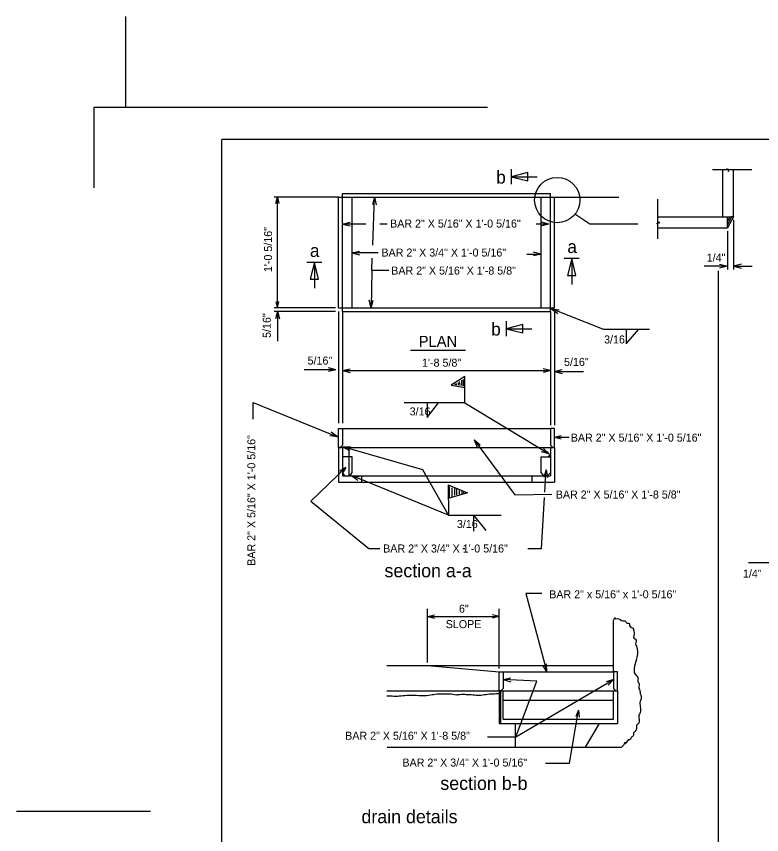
# Model space of a CAD drawing. Extents: x 973.2 to 1069.7, y 1484.4 to 1549.5.
# Drawn here: x 973.24 to 1004.28, y 1515.43 to 1549.5 of the extents above; entities that cross this region are included whole.
import ezdxf

# ---------------------------------------------------------------- set-up
doc = ezdxf.new("R2010")
doc.units = 0
for name, color, linetype in [('Level 1', 7, 'Continuous'), ('Level 2', 7, 'Continuous'), ('Level 37', 7, 'Continuous')]:
    doc.layers.add(name, color=color, linetype=linetype)

msp = doc.modelspace()

# ---------------------------------------------------------------- linework, layer by layer
at = {"layer": 'Level 1'}
for p, q in [((992.855, 1545.696), (976.473, 1545.696)), ((976.473, 1545.696), (976.473, 1542.36)), ((981.8, 1488.431), (981.8, 1544.364)), ((1065.368, 1544.364), (981.8, 1544.364)), ((993.409, 1520.047), (993.409, 1521.427))]:
    msp.add_line(p, q, dxfattribs=at)
at = {"layer": 'Level 2'}
for p, q in [((977.804, 1545.696), (977.804, 1549.495)), ((993.843, 1543.13), (993.843, 1542.506)), ((1002.223, 1543.118), (1002.829, 1543.118)), ((1002.666, 1541.155), (1002.666, 1543.122)), ((1002.829, 1543.118), (1002.853, 1543.163)), ((1002.853, 1543.163), (1002.898, 1543.04)), ((1002.898, 1543.04), (1002.905, 1543.118)), ((1002.905, 1543.118), (1003.872, 1543.118)), ((1003.1, 1541.155), (1003.1, 1543.122)), ((993.843, 1542.818), (994.921, 1542.818)), ((986.661, 1541.961), (983.97, 1541.961)), ((984.11, 1537.367), (984.11, 1541.961)), ((986.661, 1541.961), (995.651, 1541.961)), ((986.661, 1537.367), (986.661, 1541.961)), ((986.824, 1542.124), (995.487, 1542.124)), ((986.824, 1537.203), (986.824, 1542.124)), ((987.218, 1537.367), (987.218, 1541.961)), ((988.159, 1541.961), (988.068, 1541.649)), ((988.079, 1539.964), (988.159, 1541.961)), ((988.159, 1541.961), (988.225, 1541.643)), ((995.093, 1537.367), (995.093, 1541.961)), ((995.487, 1537.203), (995.487, 1542.124)), ((995.651, 1537.367), (995.651, 1541.961)), ((995.651, 1541.961), (998.335, 1541.961)), ((999.958, 1540.92), (999.958, 1541.888)), ((996.497, 1541.273), (997.126, 1540.854)), ((986.825, 1540.85), (987.14, 1540.928)), ((995.409, 1540.85), (995.126, 1540.921)), ((999.913, 1540.869), (1000.036, 1540.914)), ((999.958, 1541.155), (1003.1, 1541.155)), ((1000.036, 1540.914), (999.958, 1540.92)), ((1003.032, 1541.172), (1002.855, 1540.833)), ((1003.1, 1541.155), (1002.855, 1540.687)), ((1002.855, 1540.687), (1002.855, 1541.137)), ((1002.954, 1541.161), (1002.864, 1540.989)), ((1003.1, 1541.025), (1003.1, 1538.96)), ((986.825, 1540.85), (987.14, 1540.771)), ((987.791, 1540.85), (986.825, 1540.85)), ((988.682, 1540.85), (988.38, 1540.85)), ((995.409, 1540.85), (994.885, 1540.85)), ((995.409, 1540.85), (995.126, 1540.779)), ((997.126, 1540.854), (999.126, 1540.854)), ((999.958, 1540.845), (999.913, 1540.869)), ((999.958, 1540.239), (999.958, 1540.845)), ((999.958, 1540.687), (1002.855, 1540.687)), ((1002.855, 1540.557), (1002.855, 1538.96)), ((987.218, 1539.647), (987.533, 1539.726)), ((988.306, 1539.647), (987.218, 1539.647)), ((987.218, 1539.647), (987.533, 1539.568)), ((994.504, 1539.598), (995.095, 1539.598)), ((995.095, 1539.598), (994.78, 1539.676)), ((995.095, 1539.598), (994.78, 1539.519)), ((985.962, 1539.252), (985.338, 1539.252)), ((985.65, 1539.252), (985.65, 1538.173)), ((988.036, 1538.91), (988.057, 1539.425)), ((996.68, 1539.414), (996.056, 1539.414)), ((996.368, 1539.414), (996.368, 1538.336)), ((988.036, 1538.91), (988.012, 1537.367)), ((988.749, 1538.91), (988.036, 1538.91)), ((1002.855, 1539.09), (1001.878, 1539.09)), ((1002.483, 1514.351), (1002.483, 1538.904)), ((1003.1, 1539.09), (1003.882, 1539.09)), ((988.012, 1537.367), (987.938, 1537.683)), ((988.012, 1537.367), (988.095, 1537.68)), ((986.529, 1537.367), (983.978, 1537.367)), ((986.529, 1537.203), (983.978, 1537.203)), ((984.116, 1537.217), (984.037, 1536.902)), ((984.116, 1537.217), (984.116, 1535.973)), ((984.116, 1537.217), (984.195, 1536.902)), ((986.661, 1537.367), (995.651, 1537.367)), ((986.661, 1537.203), (986.661, 1532.565)), ((986.824, 1537.203), (995.487, 1537.203)), ((986.824, 1537.203), (986.824, 1532.565)), ((995.487, 1537.203), (995.487, 1532.474)), ((997.66, 1536.477), (995.524, 1537.315)), ((995.524, 1537.315), (995.846, 1537.273)), ((995.524, 1537.315), (995.788, 1537.126)), ((995.651, 1537.203), (995.651, 1532.474)), ((993.633, 1536.802), (993.633, 1536.178)), ((993.633, 1536.49), (994.711, 1536.49)), ((997.66, 1536.477), (999.599, 1536.477)), ((998.635, 1536.477), (998.635, 1535.86)), ((998.635, 1535.86), (999.157, 1536.477)), ((989.657, 1535.596), (991.94, 1535.596)), ((986.548, 1534.786), (985.231, 1534.786)), ((986.548, 1534.786), (986.233, 1534.865)), ((986.548, 1534.786), (986.233, 1534.707)), ((986.824, 1534.745), (987.139, 1534.824)), ((995.487, 1534.745), (995.172, 1534.824)), ((995.651, 1534.71), (995.966, 1534.789)), ((986.824, 1534.745), (995.487, 1534.745)), ((986.824, 1534.745), (987.139, 1534.666)), ((991.92, 1534.495), (991.353, 1534.145)), ((991.92, 1533.408), (991.92, 1534.495)), ((995.487, 1534.745), (995.172, 1534.666)), ((995.651, 1534.71), (996.858, 1534.71)), ((995.651, 1534.71), (995.966, 1534.631)), ((991.353, 1534.145), (991.92, 1534.041)), ((991.523, 1534.145), (991.495, 1534.202)), ((991.57, 1534.145), (991.57, 1534.212)), ((991.655, 1534.145), (991.655, 1534.24)), ((991.722, 1534.127), (991.693, 1534.287)), ((991.797, 1534.127), (991.797, 1534.354)), ((991.863, 1534.098), (991.863, 1534.372)), ((983.102, 1532.724), (983.102, 1533.413)), ((983.102, 1533.413), (986.613, 1531.987)), ((991.92, 1533.408), (989.387, 1533.408)), ((990.351, 1533.408), (990.351, 1532.791)), ((990.351, 1532.791), (990.814, 1533.408)), ((991.92, 1533.408), (995.421, 1531.276)), ((986.613, 1531.987), (986.291, 1532.033)), ((986.613, 1531.987), (986.35, 1532.179)), ((986.661, 1531.546), (986.661, 1532.334)), ((986.661, 1532.334), (986.824, 1532.334)), ((986.824, 1532.334), (995.487, 1532.334)), ((986.825, 1532.334), (986.825, 1531.64)), ((995.486, 1532.334), (995.486, 1531.64)), ((995.65, 1532.334), (995.487, 1532.334)), ((995.65, 1531.546), (995.65, 1532.334)), ((995.65, 1531.978), (995.934, 1532.046)), ((992.308, 1531.865), (994.002, 1529.581)), ((992.308, 1531.865), (992.559, 1531.658)), ((992.308, 1531.865), (992.432, 1531.565)), ((995.65, 1531.978), (996.258, 1531.973)), ((995.65, 1531.978), (995.933, 1531.904)), ((986.661, 1531.546), (995.651, 1531.546)), ((986.661, 1531.546), (986.661, 1530.103)), ((986.73, 1531.546), (986.661, 1531.546)), ((986.825, 1531.64), (986.73, 1531.546)), ((986.748, 1531.546), (986.824, 1531.546)), ((986.824, 1531.546), (986.824, 1530.365)), ((990.169, 1530.61), (986.839, 1531.58)), ((986.839, 1531.58), (987.164, 1531.568)), ((986.839, 1531.58), (987.119, 1531.417)), ((987.084, 1531.546), (987.084, 1530.365)), ((995.421, 1531.276), (995.111, 1531.372)), ((995.421, 1531.276), (995.193, 1531.507)), ((995.486, 1531.64), (995.581, 1531.546)), ((995.487, 1531.546), (995.487, 1530.365)), ((995.581, 1531.546), (995.65, 1531.546)), ((995.651, 1531.546), (995.651, 1530.103)), ((987.218, 1531.153), (986.824, 1531.153)), ((986.824, 1531.153), (986.824, 1530.488)), ((987.218, 1530.498), (987.218, 1531.153)), ((995.094, 1530.497), (995.094, 1531.153)), ((995.094, 1531.153), (995.487, 1531.153)), ((995.394, 1531.153), (995.488, 1531.248)), ((995.488, 1531.153), (995.488, 1530.497)), ((986.963, 1530.708), (985.502, 1529.31)), ((986.963, 1530.708), (986.709, 1530.563)), ((986.963, 1530.708), (986.807, 1530.46)), ((986.824, 1530.488), (986.931, 1530.365)), ((986.824, 1530.365), (995.487, 1530.365)), ((986.931, 1530.365), (987.124, 1530.365)), ((987.124, 1530.365), (987.218, 1530.498)), ((991.231, 1528.722), (987.201, 1530.381)), ((987.201, 1530.381), (987.522, 1530.334)), ((987.201, 1530.381), (987.462, 1530.189)), ((987.612, 1530.382), (987.612, 1530.114)), ((991.231, 1528.722), (990.169, 1530.61)), ((994.7, 1530.357), (994.7, 1530.114)), ((995.094, 1530.497), (995.188, 1530.366)), ((995.356, 1530.366), (995.188, 1530.366)), ((995.303, 1530.612), (995.206, 1530.303)), ((995.248, 1529.69), (995.303, 1530.612)), ((995.303, 1530.612), (995.363, 1530.293)), ((995.356, 1530.366), (995.488, 1530.497)), ((986.661, 1530.103), (995.651, 1530.103)), ((991.222, 1529.998), (991.231, 1528.722)), ((991.222, 1529.998), (992.025, 1529.657)), ((992.025, 1529.657), (991.226, 1529.421)), ((991.274, 1529.459), (991.274, 1529.918)), ((991.387, 1529.506), (991.387, 1529.87)), ((991.501, 1529.558), (991.501, 1529.847)), ((991.586, 1529.577), (991.586, 1529.804)), ((991.69, 1529.605), (991.69, 1529.761)), ((991.803, 1529.62), (991.803, 1529.743)), ((991.874, 1529.643), (991.874, 1529.686)), ((985.502, 1529.31), (987.915, 1527.347)), ((994.002, 1529.581), (995.536, 1529.596)), ((995.108, 1527.347), (995.235, 1529.47)), ((991.231, 1528.722), (993.433, 1528.722)), ((992.271, 1528.722), (992.271, 1528.061)), ((992.271, 1528.722), (992.796, 1528.088)), ((987.915, 1527.347), (988.375, 1527.347)), ((991.83, 1527.347), (991.918, 1527.347)), ((994.546, 1527.347), (995.108, 1527.347)), ((1003.734, 1526.756), (1005.349, 1526.756)), ((995.12, 1525.468), (994.457, 1525.468)), ((994.457, 1525.468), (995.332, 1522.209)), ((990.365, 1522.601), (990.365, 1524.831)), ((990.372, 1524.509), (990.655, 1524.58)), ((993.351, 1524.509), (993.067, 1524.58)), ((993.351, 1522.34), (993.351, 1524.831)), ((990.372, 1524.509), (993.351, 1524.509)), ((990.372, 1524.509), (990.655, 1524.439)), ((993.351, 1524.509), (993.067, 1524.439)), ((998.109, 1522.471), (998.109, 1524.34)), ((995.332, 1522.209), (995.318, 1522.533)), ((988.661, 1522.471), (998.109, 1522.471)), ((990.365, 1522.471), (993.351, 1522.209)), ((993.351, 1521.421), (993.351, 1522.209)), ((993.351, 1522.209), (993.514, 1522.209)), ((993.515, 1522.209), (998.109, 1522.209)), ((993.515, 1522.209), (993.515, 1521.516)), ((995.332, 1522.209), (995.167, 1522.489)), ((998.109, 1522.209), (998.109, 1522.471)), ((998.272, 1522.209), (998.109, 1522.209)), ((998.109, 1522.209), (998.109, 1521.516)), ((998.272, 1521.421), (998.272, 1522.209)), ((993.515, 1521.887), (993.833, 1521.949)), ((994.911, 1521.813), (993.515, 1521.887)), ((993.515, 1521.887), (993.825, 1521.792)), ((994.035, 1519.5), (998.109, 1521.887)), ((994.035, 1519.5), (994.911, 1521.813)), ((998.109, 1521.887), (997.799, 1521.788)), ((998.109, 1521.887), (997.883, 1521.654)), ((993.515, 1521.516), (993.42, 1521.421)), ((998.109, 1521.516), (998.203, 1521.421)), ((988.661, 1521.421), (998.273, 1521.421)), ((993.42, 1521.421), (993.351, 1521.421)), ((993.351, 1521.421), (993.351, 1520.056)), ((993.515, 1521.421), (998.109, 1521.421)), ((993.515, 1521.028), (993.515, 1521.421)), ((998.109, 1521.028), (998.109, 1521.421)), ((998.203, 1521.421), (998.272, 1521.421)), ((998.273, 1521.421), (998.273, 1520.056)), ((993.515, 1521.028), (998.109, 1521.028)), ((993.515, 1520.24), (993.515, 1521.028)), ((998.109, 1520.24), (998.109, 1521.028)), ((996.28, 1518.41), (996.648, 1520.61)), ((996.648, 1520.61), (996.531, 1520.342)), ((996.648, 1520.61), (996.671, 1520.318)), ((993.515, 1520.24), (998.109, 1520.24)), ((993.351, 1520.056), (998.273, 1520.056)), ((994.012, 1520.056), (994.012, 1519.067)), ((997.505, 1520.056), (996.933, 1519.071)), ((992.858, 1519.5), (994.035, 1519.5)), ((988.677, 1519.071), (998.458, 1519.071)), ((995.275, 1518.41), (996.28, 1518.41))]:
    msp.add_line(p, q, dxfattribs=at)
for points in [[(994.546, 1542.994), (993.843, 1542.818), (994.546, 1542.642)], [(985.826, 1538.548), (985.65, 1539.252), (985.475, 1538.548)], [(996.544, 1538.711), (996.368, 1539.414), (996.192, 1538.711)], [(994.336, 1536.666), (993.633, 1536.49), (994.336, 1536.315)]]:
    msp.add_lwpolyline(points, close=True, dxfattribs=at)
for points in [[(984.044, 1541.698), (984.11, 1541.961), (984.175, 1541.698)], [(1002.521, 1539.174), (1002.855, 1539.09), (1002.521, 1539.007)], [(1003.434, 1539.174), (1003.1, 1539.09), (1003.434, 1539.007)], [(984.044, 1537.629), (984.11, 1537.367), (984.175, 1537.629)]]:
    msp.add_lwpolyline(points, dxfattribs=at)
msp.add_circle((995.763, 1541.848), 0.944, dxfattribs=at)
for points in [[(998.109, 1524.34), (998.172, 1524.452), (998.172, 1524.42), (998.267, 1524.42), (998.489, 1524.325), (998.585, 1524.325), (998.68, 1524.23), (998.743, 1524.23), (998.775, 1524.166), (998.775, 1524.134), (998.934, 1523.976), (998.934, 1523.944), (998.966, 1523.849), (998.966, 1523.595), (999.029, 1523.563), (999.029, 1523.372), (999.061, 1523.277), (999.061, 1522.737), (999.061, 1522.039), (999.125, 1521.975), (999.125, 1521.785), (999.156, 1521.753), (999.156, 1521.562), (999.22, 1521.372), (999.22, 1521.308), (999.252, 1521.213), (999.252, 1521.181), (999.252, 1521.086), (999.22, 1520.991), (999.22, 1520.514), (999.156, 1520.356), (999.156, 1520.07), (999.125, 1520.038), (999.061, 1519.943), (999.061, 1519.879), (999.029, 1519.752), (998.934, 1519.657), (998.934, 1519.562), (998.839, 1519.467), (998.775, 1519.371), (998.743, 1519.371), (998.585, 1519.213), (998.585, 1519.276), (998.553, 1519.213), (998.489, 1519.117), (998.454, 1519.091)], [(991.56, 1521.236), (991.269, 1521.277), (990.962, 1521.277), (990.683, 1521.263), (990.418, 1521.221), (989.582, 1521.221), (989.261, 1521.193), (988.661, 1521.193)], [(993.351, 1521.292), (993.072, 1521.279), (992.798, 1521.255), (992.518, 1521.217), (992.251, 1521.236), (991.977, 1521.255), (991.71, 1521.255), (991.56, 1521.236)]]:
    msp.add_spline(points, degree=3, dxfattribs=at)
at = {"layer": 'Level 37'}
msp.add_line((978.831, 1516.397), (973.24, 1516.397), dxfattribs=at)

# ---------------------------------------------------------------- texts
at = {"layer": 'Level 2'}
for s, height, rotation, p in [('b ', 0.5333, 360, (993.225, 1542.534)), ('1\'-0 5/16"', 0.3333, 90, (983.887, 1538.847)), ('a ', 0.5333, 360, (985.466, 1539.479)), ('a ', 0.5333, 360, (996.184, 1539.642)), ('5/16"', 0.3333, 90, (983.835, 1536.108)), ('b ', 0.5333, 360, (993.015, 1536.206)), ('BAR 2" X 5/16" X 1\'-0 5/16"', 0.33333, 90, (983.192, 1526.621)), ('BAR 2" X 5/16" X 1\'-0 5/16"', 0.33333, 360, (996.326, 1531.79))]:
    msp.add_text(s, height=height, rotation=rotation, dxfattribs=at).set_placement(p)
for s, height, p in [('BAR 2" X 5/16" X 1\'-0 5/16"', 0.33333, (988.802, 1540.702)), ('BAR 2" X 3/4" X 1\'-0 5/16"', 0.33333, (988.442, 1539.496)), ('1/4" ', 0.3333, (1001.988, 1539.285)), ('BAR 2" X 5/16" X 1\'-8 5/8"', 0.33333, (988.851, 1538.745)), ('PLAN', 0.4593, (989.993, 1535.735)), ('3/16', 0.3333, (997.714, 1535.877)), ('5/16"', 0.3333, (985.367, 1534.998)), ('1\'-8 5/8"', 0.3333, (990.132, 1534.909)), ('5/16"', 0.3333, (996.046, 1534.941)), ('3/16', 0.3333, (989.618, 1532.882)), ('BAR 2" X 5/16" X 1\'-8 5/8"', 0.33333, (995.702, 1529.421)), ('3/16', 0.3333, (991.586, 1528.193)), ('BAR 2" X 3/4" X 1\'-0 5/16"', 0.33333, (988.513, 1527.174)), ('section a-a', 0.555, (988.571, 1526.142)), ('1/4"', 0.3333, (1003.496, 1526.132)), ('BAR 2" x 5/16" x 1\'-0 5/16"', 0.33333, (995.428, 1525.267)), ('6"', 0.3333, (991.671, 1524.669)), ('SLOPE', 0.3333, (991.12, 1524.025)), ('BAR 2" X 5/16" X 1\'-8 5/8"', 0.33333, (986.932, 1519.379)), ('BAR 2" X 3/4" X 1\'-0 5/16"', 0.33333, (989.316, 1518.262)), ('section b-b', 0.555, (990.896, 1517.289)), ('drain details', 0.555, (987.61, 1515.902))]:
    msp.add_text(s, height=height, dxfattribs=at).set_placement(p)

doc.saveas('drawing.dxf')
